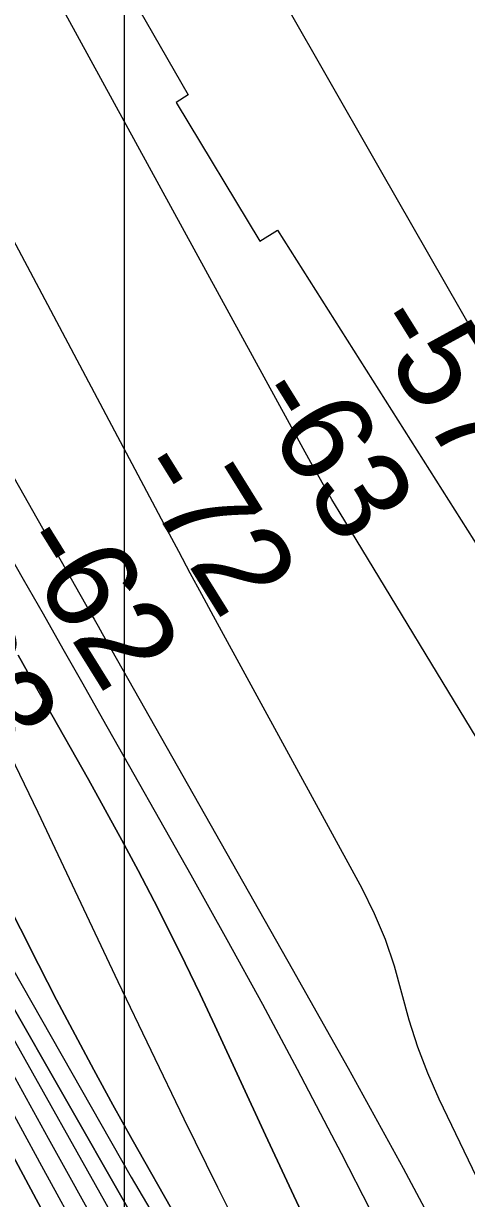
# Model space of a CAD drawing. Extents: x 3279314 to 3317160, y 734079 to 759431.
# Drawn here: x 3286005 to 3286325, y 754513 to 755360 of the extents above; entities that cross this region are included whole.
import ezdxf

# ---------------------------------------------------------------- set-up
doc = ezdxf.new("R2010")
doc.units = 0
for name, color, linetype in [('V-GRID-MAJR', 7, 'Continuous'), ('V-RIVR-RANG', 7, 'Continuous'), ('V-RRAP-RVMT', 7, 'Continuous'), ('V-TOPO-DPTH', 7, 'Continuous'), ('V-TOPO-MAJR', 7, 'Continuous'), ('V-TOPO-MINR', 7, 'Continuous'), ('V-TOPO-WATR', 7, 'Continuous')]:
    doc.layers.add(name, color=color, linetype=linetype)

msp = doc.modelspace()

# ---------------------------------------------------------------- linework, layer by layer
at = {"layer": 'V-GRID-MAJR'}
msp.add_spline([(3286080.65, 739457.23), (3286079.77, 745517.97), (3286078.89, 751579.8), (3286078.01, 757641.66), (3286078.01, 757642.71)], degree=3, dxfattribs=at)
at = {"layer": 'V-RRAP-RVMT'}
for p, q in [((3286049.69, 755438.17), (3286124.06, 755308.87)), ((3286124.06, 755308.87), (3286115.43, 755303.31)), ((3286115.43, 755303.31), (3286175.82, 755203.14)), ((3286175.82, 755203.14), (3286188.53, 755211.22)), ((3286188.53, 755211.22), (3286391.8, 754889.98))]:
    msp.add_line(p, q, dxfattribs=at)
at = {"layer": 'V-TOPO-DPTH'}
for p, q in [((3286008.18, 754892.52), (3286001.41, 754904.45)), ((3286008.18, 754892.52), (3286001.41, 754904.45)), ((3286014.95, 754880.58), (3286008.18, 754892.52)), ((3286014.95, 754880.58), (3286008.18, 754892.52)), ((3286021.72, 754868.63), (3286014.95, 754880.58)), ((3286021.72, 754868.63), (3286014.95, 754880.58)), ((3286052.22, 754814.76), (3286021.72, 754868.63)), ((3286052.22, 754814.76), (3286021.72, 754868.63)), ((3286064.38, 754792.99), (3286052.22, 754814.76)), ((3286064.38, 754792.99), (3286052.22, 754814.76)), ((3286076.37, 754771.13), (3286064.38, 754792.99)), ((3286076.37, 754771.13), (3286064.38, 754792.99)), ((3286088.1, 754749.12), (3286076.37, 754771.13)), ((3286088.1, 754749.12), (3286076.37, 754771.13)), ((3286099.66, 754727.03), (3286088.1, 754749.12)), ((3286099.66, 754727.03), (3286088.1, 754749.12)), ((3286110.94, 754704.8), (3286099.66, 754727.03)), ((3286110.94, 754704.8), (3286099.66, 754727.03)), ((3286122.03, 754682.47), (3286110.94, 754704.8)), ((3286122.03, 754682.47), (3286110.94, 754704.8)), ((3286132.84, 754660), (3286122.03, 754682.47)), ((3286132.84, 754660), (3286122.03, 754682.47)), ((3286143.44, 754637.43), (3286132.84, 754660)), ((3286143.44, 754637.43), (3286132.84, 754660)), ((3286180.06, 754558.18), (3286143.44, 754637.43)), ((3286180.06, 754558.18), (3286143.44, 754637.43)), ((3286209, 754496), (3286180.06, 754558.18)), ((3286209, 754496), (3286180.06, 754558.18))]:
    msp.add_line(p, q, dxfattribs=at)
for points in [[(3286018.11, 754505.46), (3285995.94, 754546.77), (3285973.71, 754588.05), (3285951.39, 754629.27), (3285929, 754670.47), (3285879.57, 754761.19), (3285868.08, 754782.48), (3285856.72, 754803.84), (3285845.53, 754825.29), (3285834.47, 754846.81), (3285533.28, 755438.71), (3285503.85, 755498.81), (3285475.69, 755559.48), (3285449.4, 755620.98), (3285424.37, 755683.04), (3285396.65, 755754.96), (3285386.88, 755781.63), (3285377.72, 755808.5), (3285369.48, 755835.66), (3285361.84, 755863.01), (3285059.4, 757021.6)], [(3285501.13, 755812.64), (3285815.9, 755182.28), (3285842.05, 755130.42), (3285868.45, 755078.69), (3285895.25, 755027.16), (3285922.31, 754975.77), (3285934.23, 754953.32), (3285955.25, 754913.11), (3285975.89, 754872.72), (3285995.97, 754832.04), (3286015.68, 754791.18), (3286073.54, 754669.11), (3286097.22, 754619.57), (3286121.11, 754570.14), (3286145.33, 754520.86), (3286169.77, 754471.69)], [(3285501.13, 755812.64), (3285815.9, 755182.28), (3285842.05, 755130.42), (3285868.45, 755078.69), (3285895.25, 755027.16), (3285922.31, 754975.77), (3285934.23, 754953.32), (3285955.25, 754913.11), (3285975.89, 754872.72), (3285995.97, 754832.04), (3286015.68, 754791.18), (3286073.54, 754669.11), (3286097.22, 754619.57), (3286121.11, 754570.14), (3286145.33, 754520.86), (3286169.77, 754471.69)], [(3285420.27, 755806.21), (3285867.09, 754884.46), (3285871.66, 754875.18), (3285876.3, 754865.95), (3285881.05, 754856.76), (3285885.87, 754847.62), (3285894.93, 754830.71), (3285895.29, 754830.05), (3285895.65, 754829.39), (3285896.01, 754828.74), (3285896.38, 754828.09), (3286025.02, 754602.95), (3286088.7, 754491.53)], [(3286088.7, 754491.53), (3286025.02, 754602.95), (3285896.38, 754828.09), (3285896.01, 754828.74), (3285895.65, 754829.39), (3285895.29, 754830.05), (3285894.93, 754830.71), (3285885.87, 754847.62), (3285881.05, 754856.76), (3285876.3, 754865.95), (3285871.66, 754875.18), (3285867.09, 754884.46), (3285420.27, 755806.21)], [(3285579.7, 755421.18), (3285626.54, 755319.24), (3285674.51, 755217.84), (3285724.17, 755117.26), (3285774.95, 755017.23), (3285867.94, 754837.79), (3285873.12, 754827.9), (3285878.35, 754818.04), (3285883.67, 754808.23), (3285889.03, 754798.44), (3285983.33, 754628.18), (3286023.22, 754556.14), (3286063.1, 754484.11)], [(3285579.7, 755421.18), (3285626.54, 755319.24), (3285674.51, 755217.84), (3285724.17, 755117.26), (3285774.95, 755017.23), (3285867.94, 754837.79), (3285873.12, 754827.9), (3285878.35, 754818.04), (3285883.67, 754808.23), (3285889.03, 754798.44), (3285983.33, 754628.18), (3286023.22, 754556.14), (3286063.1, 754484.11)], [(3286148.63, 754440.57), (3286083.88, 754555.15), (3286069.9, 754580.19), (3286056.11, 754605.32), (3286042.59, 754630.6), (3286029.25, 754655.98), (3286016.12, 754681.48), (3286003.09, 754707.01), (3285990.2, 754732.63), (3285977.4, 754758.29), (3285950.22, 754813.19), (3285941.21, 754831.2), (3285932.09, 754849.14), (3285922.82, 754867.01), (3285913.44, 754884.83), (3285634.52, 755409.01)], [(3286148.63, 754440.57), (3286083.88, 754555.15), (3286069.9, 754580.19), (3286056.11, 754605.32), (3286042.59, 754630.6), (3286029.25, 754655.98), (3286016.12, 754681.48), (3286003.09, 754707.01), (3285990.2, 754732.63), (3285977.4, 754758.29), (3285950.22, 754813.19), (3285941.21, 754831.2), (3285932.09, 754849.14), (3285922.82, 754867.01), (3285913.44, 754884.83), (3285634.52, 755409.01)]]:
    msp.add_lwpolyline(points, dxfattribs=at)
at = {"layer": 'V-TOPO-MAJR'}
msp.add_lwpolyline([(3285759.33, 755392.26), (3286005.21, 754959.44), (3286019.51, 754934.24), (3286033.81, 754909.04), (3286048.1, 754883.83), (3286062.39, 754858.62), (3286126.16, 754745.97), (3286152.15, 754699.47), (3286177.79, 754652.77), (3286202.9, 754605.79), (3286227.67, 754558.62), (3286234.59, 754545.25), (3286255.38, 754504.5)], dxfattribs=at)
at = {"layer": 'V-TOPO-MINR'}
for p, q in [((3286001.41, 754904.45), (3286008.18, 754892.52)), ((3286008.18, 754892.52), (3286014.95, 754880.58)), ((3286014.95, 754880.58), (3286021.72, 754868.63)), ((3286021.72, 754868.63), (3286052.22, 754814.76)), ((3286052.22, 754814.76), (3286064.38, 754792.99)), ((3286064.38, 754792.99), (3286076.37, 754771.13)), ((3286076.37, 754771.13), (3286088.1, 754749.12)), ((3286088.1, 754749.12), (3286099.66, 754727.03)), ((3286099.66, 754727.03), (3286110.94, 754704.8)), ((3286110.94, 754704.8), (3286122.03, 754682.47)), ((3286122.03, 754682.47), (3286132.84, 754660)), ((3286132.84, 754660), (3286143.44, 754637.43)), ((3286143.44, 754637.43), (3286180.06, 754558.18)), ((3286180.06, 754558.18), (3286209, 754496))]:
    msp.add_line(p, q, dxfattribs=at)
for points in [[(3285059.4, 757021.6), (3285361.84, 755863.01), (3285369.48, 755835.66), (3285377.72, 755808.5), (3285386.88, 755781.63), (3285396.65, 755754.96), (3285424.37, 755683.04), (3285449.4, 755620.98), (3285475.69, 755559.48), (3285503.85, 755498.81), (3285533.28, 755438.71), (3285834.47, 754846.81), (3285845.53, 754825.29), (3285856.72, 754803.84), (3285868.08, 754782.48), (3285879.57, 754761.19), (3285929, 754670.47), (3285951.39, 754629.27), (3285973.71, 754588.05), (3285995.94, 754546.77), (3286018.11, 754505.46)], [(3286332.59, 755132.82), (3286262.87, 755254.53), (3286220.91, 755327.89), (3286179, 755401.29), (3286137.19, 755474.74), (3286095.43, 755548.23), (3285868.95, 755947.42), (3285855.64, 755971.5), (3285842.7, 755995.78), (3285830.31, 756020.35), (3285818.3, 756045.1), (3285781.59, 756122.94), (3285768.37, 756151.03), (3285755.19, 756179.14)], [(3285501.13, 755812.64), (3285815.9, 755182.28), (3285842.05, 755130.42), (3285868.45, 755078.69), (3285895.25, 755027.16), (3285922.31, 754975.77), (3285934.23, 754953.32), (3285955.25, 754913.11), (3285975.89, 754872.72), (3285995.97, 754832.04), (3286015.68, 754791.18), (3286073.54, 754669.11), (3286097.22, 754619.57), (3286121.11, 754570.14), (3286145.33, 754520.86), (3286169.77, 754471.69)], [(3285420.27, 755806.21), (3285867.09, 754884.46), (3285871.66, 754875.18), (3285876.3, 754865.95), (3285881.05, 754856.76), (3285885.87, 754847.62), (3285894.93, 754830.71), (3285895.29, 754830.05), (3285895.65, 754829.39), (3285896.01, 754828.74), (3285896.38, 754828.09), (3286025.02, 754602.95), (3286088.7, 754491.53)], [(3285417.09, 755798.56), (3285720.75, 755153.75), (3285747.35, 755098.22), (3285774.43, 755042.92), (3285802.23, 754987.98), (3285830.51, 754933.28), (3285882.72, 754833.88), (3285885.28, 754829.07), (3285887.85, 754824.28), (3285890.47, 754819.51), (3285893.11, 754814.75), (3286006.23, 754613.07), (3286057, 754522.6), (3286107.8, 754432.14)], [(3285800.22, 755576.52), (3286108.8, 754995.2), (3286117.11, 754979.6), (3286125.45, 754964.03), (3286133.85, 754948.48), (3286142.28, 754932.95), (3286249.45, 754736.39), (3286258.42, 754718.22), (3286266.37, 754699.65), (3286272.78, 754680.51), (3286278.17, 754660.97), (3286283.42, 754641.36), (3286289.5, 754622.04), (3286296.83, 754603.17), (3286304.99, 754584.58), (3286338.13, 754515.41)], [(3285728.07, 755510.37), (3286053.33, 754935.75), (3286056.26, 754930.57), (3286059.19, 754925.4), (3286062.13, 754920.22), (3286065.06, 754915.05), (3286199.3, 754678.35), (3286239.51, 754606.53), (3286279.2, 754534.43), (3286318.09, 754461.9)], [(3285634.52, 755409.01), (3285913.44, 754884.83), (3285922.82, 754867.01), (3285932.09, 754849.14), (3285941.21, 754831.2), (3285950.22, 754813.19), (3285977.4, 754758.29), (3285990.2, 754732.63), (3286003.09, 754707.01), (3286016.12, 754681.48), (3286029.25, 754655.98), (3286042.59, 754630.6), (3286056.11, 754605.32), (3286069.9, 754580.19), (3286083.88, 754555.15), (3286148.63, 754440.57)], [(3286344.96, 754823.95), (3286233.03, 755008.2), (3286227.81, 755016.93), (3286222.67, 755025.7), (3286217.65, 755034.54), (3286212.71, 755043.42), (3286012.02, 755410.37)], [(3285575.89, 755390.4), (3285625.53, 755286.2), (3285676.93, 755182.81), (3285851.67, 754842.16), (3285859.72, 754826.63), (3285867.85, 754811.15), (3285876.11, 754795.74), (3285884.46, 754780.37), (3285957.35, 754647.54), (3285987.89, 754591.82), (3286018.39, 754536.08), (3286048.83, 754480.3)], [(3285632.84, 755385.62), (3285678.22, 755293.83), (3285724.09, 755202.29), (3285770.69, 755111.11), (3285817.77, 755020.18), (3285904.36, 754854.55), (3285908.48, 754846.6), (3285912.57, 754838.64), (3285916.6, 754830.65), (3285920.59, 754822.65), (3285932.09, 754799.43), (3285938.08, 754787.44), (3285944.14, 754775.48), (3285950.28, 754763.56), (3285956.49, 754751.68), (3285962.81, 754739.85), (3285969.2, 754728.06), (3285975.7, 754716.34), (3285982.28, 754704.66), (3286082.99, 754528.02), (3286141.38, 754428.93)]]:
    msp.add_lwpolyline(points, dxfattribs=at)
at = {"layer": 'V-TOPO-WATR'}
msp.add_lwpolyline([(3285579.7, 755421.18), (3285626.54, 755319.24), (3285674.51, 755217.84), (3285724.17, 755117.26), (3285774.95, 755017.23), (3285867.94, 754837.79), (3285873.12, 754827.9), (3285878.35, 754818.04), (3285883.67, 754808.23), (3285889.03, 754798.44), (3285983.33, 754628.18), (3286023.22, 754556.14), (3286063.1, 754484.11)], dxfattribs=at)

# ---------------------------------------------------------------- texts
at = {"layer": 'V-RIVR-RANG'}
for s, p in [('-57', (3286251.72, 755142.95)), ('-63', (3286166.25, 755091.02)), ('-72', (3286081.34, 755038.19)), ('-62', (3285996.72, 754984.91)), ('-23', (3285909.86, 754935.22))]:
    msp.add_text(s, height=67, rotation=301.88892, dxfattribs=at).set_placement(p)

doc.saveas('drawing.dxf')
